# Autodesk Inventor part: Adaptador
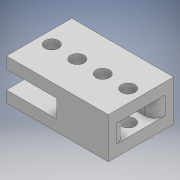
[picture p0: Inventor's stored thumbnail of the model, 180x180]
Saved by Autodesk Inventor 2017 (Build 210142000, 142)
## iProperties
Part Number: Adaptador
Material: Genérico
Document SubType Name: Modeling
Designer: Diego
Density: 1 g/cm^3
Appearance: Valor por defecto
Author: Diego
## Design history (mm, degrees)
derived "Lubina.ipt"
feature "Adaptador::Lubina.ipt" dims "d0" = 10
tag "OperaciónIdentificador1"
node "Sólido1"
